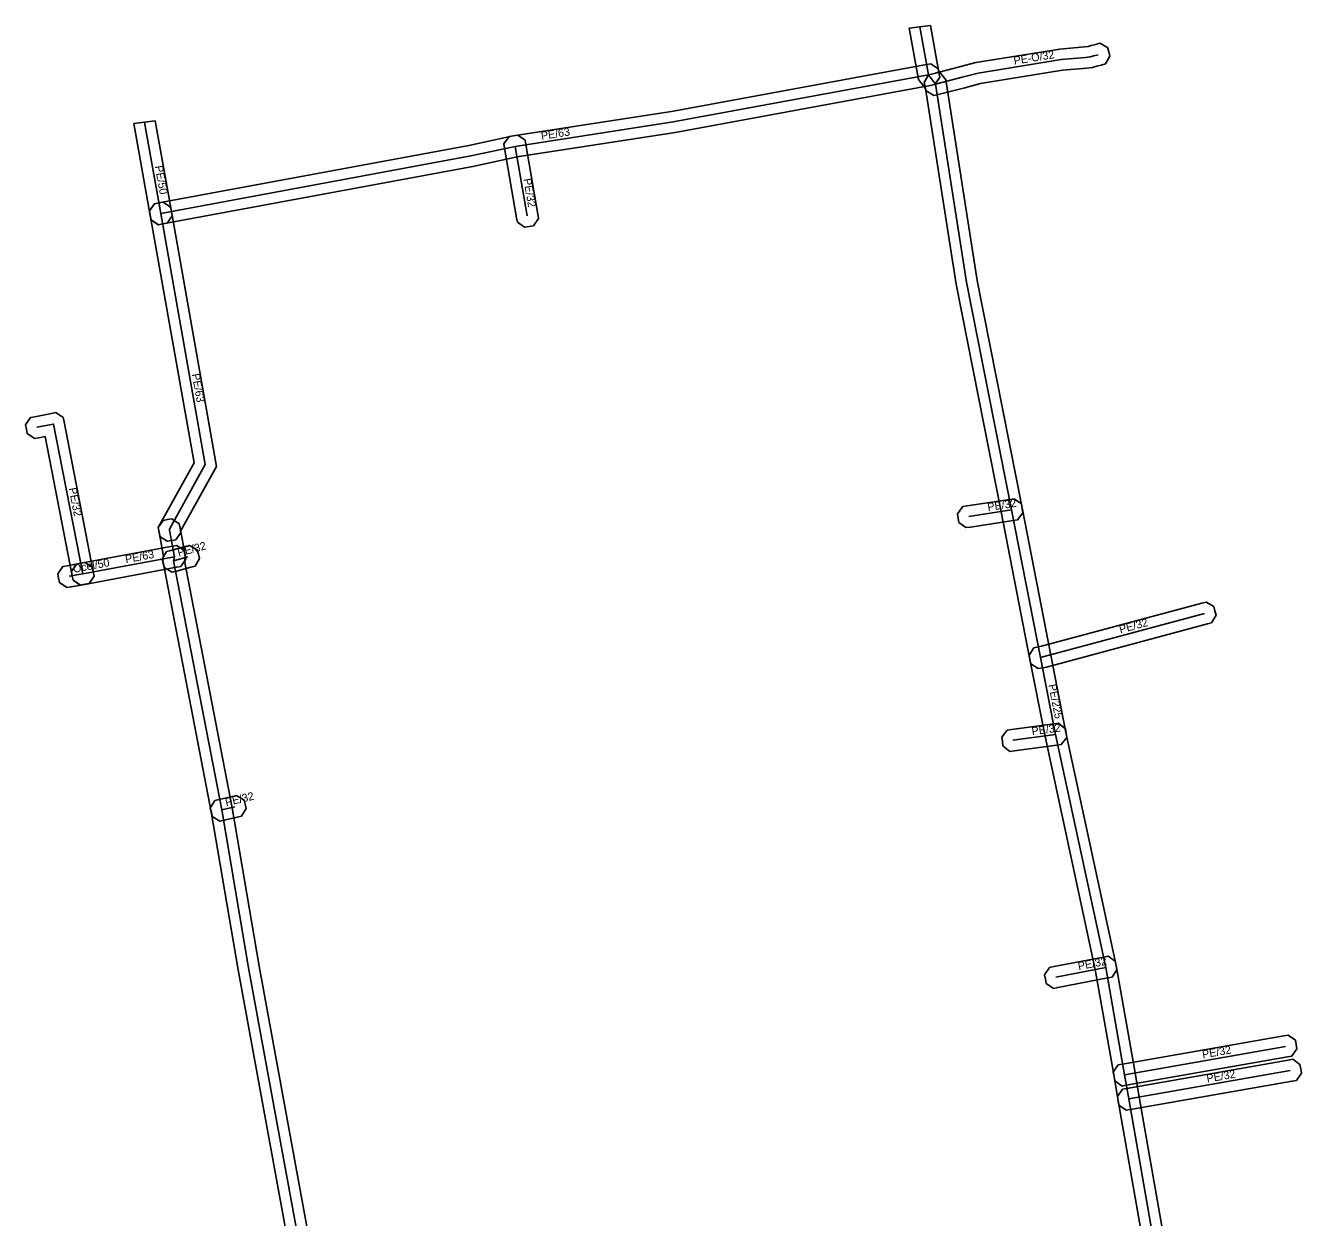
# Model space of a CAD drawing. Extents: x -710999 to -710778, y -1036229 to -1036005.
# Drawn here: x -710908.4 to -710788.8, y -1036117 to -1036005.3 of the extents above; entities that cross this region are included whole.
import ezdxf

# ---------------------------------------------------------------- set-up
doc = ezdxf.new("R2010")
doc.units = 0
for name, color, linetype in [('1', 7, 'Continuous'), ('24', 7, 'Continuous'), ('30', 7, 'Continuous')]:
    doc.layers.add(name, color=color, linetype=linetype)

msp = doc.modelspace()

# ---------------------------------------------------------------- linework, layer by layer
at = {"layer": '1'}
for points in [[(-710801.94, -1036129.34), (-710806.02, -1036106.06), (-710806.41, -1036103.8), (-710808.17, -1036093.77), (-710812.87, -1036071.95), (-710814.29, -1036064.71), (-710816.99, -1036050.9), (-710821.21, -1036029.55), (-710824.08, -1036011.22), (-710824.74, -1036010.38), (-710825.59, -1036005.57), (-710823.61, -1036005.33), (-710822.86, -1036009.54), (-710822.18, -1036010.4), (-710819.24, -1036029.2), (-710815.03, -1036050.52), (-710812.33, -1036064.33), (-710810.91, -1036071.55), (-710806.21, -1036093.39), (-710804.44, -1036103.45), (-710804.05, -1036105.72), (-710799.96, -1036129)], [(-710880.56, -1036136.99), (-710888.47, -1036093.79), (-710890.99, -1036078.99), (-710895.54, -1036055.45), (-710895.45, -1036055.07), (-710895.88, -1036052.78), (-710895.95, -1036052.37), (-710895.49, -1036051.69), (-710895.08, -1036051.61), (-710894.67, -1036051.54), (-710893.99, -1036052), (-710893.91, -1036052.41), (-710893.41, -1036055.11), (-710893.5, -1036055.49), (-710889.03, -1036078.63), (-710886.51, -1036093.45), (-710878.66, -1036136.27)]]:
    msp.add_lwpolyline(points, dxfattribs=at)
for points in [[(-710823.78, -1036009.94), (-710823.38, -1036009.84), (-710820.89, -1036009.21), (-710819.34, -1036008.8), (-710811.47, -1036007.53), (-710809.17, -1036007.33), (-710808.84, -1036007.29), (-710808.56, -1036007.21), (-710808.14, -1036007.09), (-710807.74, -1036006.99), (-710807.02, -1036007.4), (-710806.91, -1036007.8), (-710806.81, -1036008.2), (-710807.22, -1036008.92), (-710807.62, -1036009.03), (-710808.02, -1036009.13), (-710808.44, -1036009.25), (-710808.97, -1036009.32), (-710811.23, -1036009.51), (-710818.92, -1036010.76), (-710820.39, -1036011.15), (-710822.89, -1036011.78), (-710823.29, -1036011.88), (-710824, -1036011.46), (-710824.1, -1036011.06), (-710824.2, -1036010.65)], [(-710823.21, -1036010.86), (-710823.62, -1036010.94), (-710847.54, -1036015.35), (-710862.33, -1036017.63), (-710866.47, -1036018.52), (-710895.53, -1036023.91), (-710895.94, -1036023.99), (-710896.62, -1036023.52), (-710896.7, -1036023.11), (-710896.77, -1036022.7), (-710896.31, -1036022.02), (-710895.9, -1036021.95), (-710866.87, -1036016.56), (-710862.69, -1036015.67), (-710847.88, -1036013.37), (-710823.98, -1036008.97), (-710823.57, -1036008.9), (-710822.89, -1036009.37), (-710822.81, -1036009.77), (-710822.74, -1036010.18)], [(-710896.7, -1036023.11), (-710898.25, -1036014.52), (-710896.26, -1036014.27), (-710894.73, -1036022.75), (-710894.66, -1036023.16), (-710895.13, -1036023.84), (-710895.54, -1036023.91), (-710895.95, -1036023.99), (-710896.62, -1036023.52)], [(-710862.31, -1036023.74), (-710862.38, -1036023.33), (-710863.5, -1036016.82), (-710863.57, -1036016.41), (-710863.09, -1036015.73), (-710862.68, -1036015.66), (-710862.27, -1036015.59), (-710861.59, -1036016.07), (-710861.52, -1036016.48), (-710860.4, -1036022.99), (-710860.33, -1036023.4), (-710860.81, -1036024.08), (-710861.22, -1036024.15), (-710861.63, -1036024.22)], [(-710890.5, -1036046.64), (-710893.86, -1036052.69), (-710893.84, -1036052.82), (-710894.31, -1036053.5), (-710894.71, -1036053.58), (-710895.12, -1036053.65), (-710895.8, -1036053.19), (-710895.88, -1036052.78), (-710895.96, -1036052.35), (-710892.6, -1036046.29), (-710896.7, -1036023.1), (-710896.77, -1036022.7), (-710896.3, -1036022.02), (-710895.89, -1036021.94), (-710895.48, -1036021.87), (-710894.8, -1036022.35), (-710894.73, -1036022.76)], [(-710903.94, -1036057.29), (-710904.01, -1036056.88), (-710906.55, -1036043.83), (-710907.14, -1036043.94), (-710907.55, -1036044.02), (-710908.23, -1036043.56), (-710908.31, -1036043.15), (-710908.39, -1036042.74), (-710907.93, -1036042.06), (-710907.52, -1036041.98), (-710905.95, -1036041.67), (-710905.55, -1036041.59), (-710904.86, -1036042.06), (-710904.78, -1036042.46), (-710902.05, -1036056.5), (-710901.97, -1036056.91), (-710902.44, -1036057.59), (-710902.84, -1036057.67), (-710903.25, -1036057.75)], [(-710820.58, -1036050.39), (-710820.17, -1036050.33), (-710816.16, -1036049.72), (-710815.75, -1036049.66), (-710815.08, -1036050.15), (-710815.02, -1036050.56), (-710814.96, -1036050.97), (-710815.45, -1036051.64), (-710815.86, -1036051.7), (-710819.87, -1036052.31), (-710820.28, -1036052.37), (-710820.95, -1036051.88), (-710821.01, -1036051.47), (-710821.07, -1036051.06)], [(-710893.84, -1036056), (-710894.25, -1036056.07), (-710902.85, -1036057.68), (-710903.26, -1036057.75), (-710903.94, -1036057.28), (-710904.02, -1036056.88), (-710904.09, -1036056.47), (-710903.62, -1036055.79), (-710903.21, -1036055.71), (-710894.61, -1036054.11), (-710894.21, -1036054.03), (-710893.52, -1036054.5), (-710893.45, -1036054.91), (-710893.37, -1036055.31)], [(-710895.18, -1036054.61), (-710894.78, -1036054.5), (-710893.43, -1036054.14), (-710893.03, -1036054.04), (-710892.31, -1036054.45), (-710892.2, -1036054.85), (-710892.1, -1036055.25), (-710892.51, -1036055.97), (-710892.91, -1036056.08), (-710894.26, -1036056.44), (-710894.66, -1036056.54), (-710895.38, -1036056.13), (-710895.49, -1036055.73), (-710895.59, -1036055.33)], [(-710902.44, -1036057.6), (-710902.85, -1036057.68), (-710904.13, -1036057.91), (-710904.53, -1036057.99), (-710905.22, -1036057.52), (-710905.29, -1036057.11), (-710905.37, -1036056.71), (-710904.9, -1036056.02), (-710904.49, -1036055.95), (-710903.21, -1036055.71), (-710902.81, -1036055.63), (-710902.12, -1036056.1), (-710902.05, -1036056.51), (-710901.97, -1036056.92)], [(-710797.26, -1036061.28), (-710797.66, -1036061.39), (-710812.73, -1036065.43), (-710813.11, -1036065.5), (-710813.52, -1036065.58), (-710814.21, -1036065.12), (-710814.29, -1036064.71), (-710814.37, -1036064.31), (-710813.91, -1036063.62), (-710813.5, -1036063.54), (-710813.19, -1036063.47), (-710798.18, -1036059.45), (-710797.78, -1036059.35), (-710797.06, -1036059.76), (-710796.95, -1036060.16), (-710796.85, -1036060.56)], [(-710816.42, -1036071.34), (-710816.01, -1036071.29), (-710812.02, -1036070.76), (-710811.61, -1036070.7), (-710810.95, -1036071.21), (-710810.9, -1036071.62), (-710810.84, -1036072.03), (-710811.35, -1036072.69), (-710811.76, -1036072.74), (-710815.75, -1036073.27), (-710816.16, -1036073.33), (-710816.82, -1036072.82), (-710816.87, -1036072.41), (-710816.93, -1036072)], [(-710890.64, -1036077.93), (-710890.24, -1036077.84), (-710889.01, -1036077.55), (-710888.61, -1036077.45), (-710887.9, -1036077.89), (-710887.81, -1036078.29), (-710887.71, -1036078.69), (-710888.15, -1036079.4), (-710888.55, -1036079.49), (-710889.78, -1036079.78), (-710890.18, -1036079.88), (-710890.89, -1036079.44), (-710890.98, -1036079.04), (-710891.08, -1036078.64)], [(-710812.45, -1036093.57), (-710812.04, -1036093.49), (-710807.38, -1036092.6), (-710806.97, -1036092.52), (-710806.29, -1036092.98), (-710806.21, -1036093.39), (-710806.13, -1036093.8), (-710806.59, -1036094.48), (-710807, -1036094.56), (-710811.66, -1036095.45), (-710812.07, -1036095.53), (-710812.76, -1036095.07), (-710812.83, -1036094.66), (-710812.91, -1036094.25)], [(-710789.75, -1036101.89), (-710790.15, -1036101.96), (-710805.26, -1036104.61), (-710805.66, -1036104.68), (-710806.34, -1036104.21), (-710806.41, -1036103.8), (-710806.49, -1036103.39), (-710806.01, -1036102.71), (-710805.6, -1036102.64), (-710790.5, -1036099.99), (-710790.09, -1036099.92), (-710789.41, -1036100.4), (-710789.34, -1036100.8), (-710789.27, -1036101.21)], [(-710805.61, -1036104.98), (-710805.2, -1036104.9), (-710790.08, -1036102.25), (-710789.67, -1036102.18), (-710788.99, -1036102.66), (-710788.92, -1036103.06), (-710788.84, -1036103.47), (-710789.32, -1036104.15), (-710789.73, -1036104.22), (-710804.86, -1036106.87), (-710805.27, -1036106.95), (-710805.95, -1036106.47), (-710806.02, -1036106.06), (-710806.09, -1036105.65)]]:
    msp.add_lwpolyline(points, close=True, dxfattribs=at)
at = {"layer": '24'}
for points in [[(-710824.6, -1036005.45), (-710823.8, -1036009.96), (-710823.13, -1036010.81), (-710820.23, -1036029.38), (-710816.01, -1036050.71), (-710813.31, -1036064.52), (-710811.89, -1036071.75), (-710807.19, -1036093.58), (-710805.43, -1036103.62), (-710805.03, -1036105.89), (-710800.95, -1036129.17)], [(-710823.13, -1036010.81), (-710820.64, -1036010.18), (-710819.13, -1036009.78), (-710811.35, -1036008.52), (-710809.07, -1036008.32), (-710808.64, -1036008.27), (-710808.29, -1036008.17), (-710807.88, -1036008.06)], [(-710823.8, -1036009.96), (-710847.71, -1036014.36), (-710862.51, -1036016.65), (-710866.67, -1036017.54), (-710895.71, -1036022.93)], [(-710897.26, -1036014.4), (-710895.71, -1036022.93)], [(-710861.39, -1036023.16), (-710862.51, -1036016.65)], [(-710895.71, -1036022.93), (-710891.55, -1036046.46), (-710894.91, -1036052.52), (-710894.9, -1036052.59)], [(-710903.03, -1036056.69), (-710905.76, -1036042.66), (-710907.33, -1036042.96)], [(-710820.02, -1036051.32), (-710816.01, -1036050.71)], [(-710894.9, -1036052.59), (-710894.43, -1036055.09), (-710894.52, -1036055.47), (-710890.01, -1036078.81), (-710887.49, -1036093.62), (-710879.61, -1036136.63), (-710878.27, -1036138.81), (-710878.29, -1036143.06), (-710878.28, -1036143.23), (-710876.95, -1036150.93), (-710874.18, -1036166), (-710870.57, -1036191.31), (-710868.11, -1036205.15), (-710866.09, -1036216.18), (-710864.83, -1036223.01)], [(-710894.43, -1036055.09), (-710903.03, -1036056.69)], [(-710894.52, -1036055.47), (-710893.17, -1036055.11)], [(-710903.03, -1036056.69), (-710904.31, -1036056.93)], [(-710797.92, -1036060.42), (-710812.96, -1036064.45), (-710813.31, -1036064.52)], [(-710815.88, -1036072.28), (-710811.89, -1036071.75)], [(-710890.01, -1036078.81), (-710888.78, -1036078.52)], [(-710811.85, -1036094.47), (-710807.19, -1036093.58)], [(-710790.33, -1036100.98), (-710805.43, -1036103.62)], [(-710805.03, -1036105.89), (-710789.9, -1036103.24)]]:
    msp.add_lwpolyline(points, dxfattribs=at)

# ---------------------------------------------------------------- texts
at = {"layer": '30'}
for s, rotation, p in [('PE-O/32', 9.1994, (-710815.75, -1036009)), ('PE/63', 8.7956, (-710860.04, -1036016.04)), ('PE/50', 280.2462, (-710896.28, -1036018.51)), ('PE/32', 279.7618, (-710861.75, -1036019.71)), ('PE/63', 280.0374, (-710892.81, -1036037.99)), ('PE/32', 281.0019, (-710904.35, -1036048.69)), ('PE/32', 8.6495, (-710818.21, -1036050.82)), ('PE/32', 14.9314, (-710894.04, -1036055.09)), ('Ocel/50', 10.5493, (-710903.87, -1036056.61)), ('PE/63', 10.5497, (-710898.98, -1036055.7)), ('PE/32', 15.0002, (-710805.81, -1036062.28)), ('PE/225', 281.0782, (-710812.56, -1036067.1)), ('PE/32', 7.5664, (-710814.08, -1036071.82)), ('PE/32', 13.2665, (-710889.59, -1036078.47)), ('PE/32', 10.8125, (-710809.72, -1036093.83)), ('PE/32', 9.9452, (-710798.08, -1036102.1)), ('PE/32', 9.9455, (-710797.67, -1036104.36))]:
    msp.add_text(s, height=0.75, rotation=rotation, dxfattribs=at).set_placement(p)

doc.saveas('drawing.dxf')
